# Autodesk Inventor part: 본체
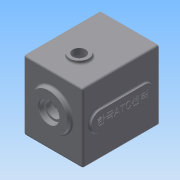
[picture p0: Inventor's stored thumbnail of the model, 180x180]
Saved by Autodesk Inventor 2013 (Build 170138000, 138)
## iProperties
Created: 2016-02
Part Number: 본체
Material: 알루미늄 6061
Document SubType Name: Modeling
Designer: mduedu
Density: 2.71 g/cm^3
Mass: 1515.93 g
Surface Area: 1077.08 cm^2
Volume: 559.383 cm^3
Author: mduedu
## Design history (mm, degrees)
sketch "스케치1"
  geometry: L1 (-47, -47)-(47, -47); L2 (47, -47)-(47, 63); L3 (47, 63)-(-47, 63); L4 (-47, 63)-(-47, -47); 2 further points
  constraints: 8 end point, 2 parallel, 1 horizontal, 1 midpoint, 1 perpendicular, 1 vertical alignment
  dimensions: "d0" = 94 distance of L2.end L3.end; "d155" = 110 distance of L1.end L2.end; "d156" = 47 distance from line of L1 point (0, 0)
extrude "돌출1" new body sketch "스케치1" distance "d2" = 120; taper "d3" = 0 deg
sketch "스케치3"
  geometry: L1 (47, -47)-(-47, -47) reference; L2 (47, 63)-(47, -47) reference; L3 (-47, 63)-(47, 63) reference; L4 (-47, -47)-(-47, 63) reference; L5 (37, 53)-(37, -37); L6 (37, -37)-(-37, -37); L7 (-37, -37)-(-37, 53); L8 (-37, 53)-(37, 53); 1 further point
  constraints: 8 end point, 3 other
  dimensions: "d226" = 10 distance between parallel lines of L8 L3
extrude "돌출3" cut sketch "스케치3" distance "d11" = 110; taper "d12" = 0 deg
sketch "스케치4"
  geometry: C1 r 21 at (0, 11); 1 further point
  constraints: 1 centre point, 1 vertical alignment
  dimensions: "d13" = 21 radius of C1; "d227" = 11 distance of point (0, 0) C1.centre
extrude "돌출4" join sketch "스케치4" distance "d16" = 7; taper "d17" = 0 deg
sketch "스케치5"
  geometry: C1 r 15 at (0, -20); 1 further point
  constraints: 1 centre point, 1 vertical alignment
  dimensions: "d18" = 15 radius of C1; "d20" = 20 distance of point (0, 0) C1.centre
extrude "돌출5" join sketch "스케치5" distance "d21" = 7; taper "d22" = 0 deg
sketch "스케치6"
  geometry: C1 r 30 at (0, 11); A1 r 21 centre (0, 11) between (8.978, -7.984) and (-8.978, -7.984) reference; 1 further point
  constraints: 1 centre point, 1 coincident
  dimensions: "d228" = 60 diameter of C1
extrude "돌출6" join sketch "스케치6" distance "d25" = 7; taper "d26" = -3 deg
hole "구멍1" diameter "d29" = 35; stored, may be unused: countersink angle "d33" = 90 deg, drill point angle "d35" = 0 deg; dims "d27" = 10, "d28" = 10, "d30" = 6, "d31" = 4, "d32" = 2, "d34" = 10
hole "구멍2" diameter "d38" = 22; stored, may be unused: countersink angle "d42" = 90 deg, drill point angle "d44" = 0 deg; dims "d36" = 10, "d37" = 10, "d39" = 6, "d40" = 4, "d41" = 2, "d43" = 7
hole "구멍3" diameter "d47" = 19; stored, may be unused: countersink angle "d51" = 90 deg, drill point angle "d53" = 0 deg; dims "d45" = 10, "d46" = 10, "d48" = 6, "d49" = 4, "d50" = 2, "d52" = 1
hole "구멍4" diameter "d56" = 32; stored, may be unused: countersink angle "d60" = 90 deg, drill point angle "d62" = 0 deg; dims "d57" = 6, "d58" = 4, "d59" = 2, "d61" = 8, "d220" = 10, "d221" = 10
hole "구멍5" diameter "d65" = 25; stored, may be unused: countersink angle "d69" = 90 deg, drill point angle "d71" = 0 deg; dims "d63" = 10, "d64" = 10, "d66" = 6, "d67" = 4, "d68" = 2, "d70" = 8
fillet "모깎기2" dims "d73" = 0.3
fillet "모깎기3" dims "d74" = 2
chamfer "모따기1" distance "d75" = 1; stored, may be unused: second distance "d76" = 2, angle "d77" = 45 deg
fillet "모깎기4" dims "d78" = 3
fillet "모깎기23" dims "d240" = 1
fillet "모깎기20" dims "d229" = 3
sketch "스케치23"
  geometry: L1 (-37, 53)-(37, 53) reference; L2 (37, 53)-(37, -37) reference; L3 (37, -37)-(-37, -37) reference; L4 (-37, -37)-(-37, 53) reference; L5 (44, -47)-(-44, -47) reference; L6 (47, 60)-(47, -44) reference; L7 (-44, 63)-(44, 63) reference; L8 (-47, -44)-(-47, 60) reference; C1 r 10 at (-37, 53); C2 r 10 at (37, 53); C3 r 10 at (-37, -37); C4 r 10 at (37, -37); A1 r 3 centre (-44, -44) between (-47, -44) and (-44, -47) reference; A2 r 3 centre (44, -44) between (44, -47) and (47, -44) reference; A3 r 3 centre (44, 60) between (47, 60) and (44, 63) reference; A4 r 3 centre (-44, 60) between (-44, 63) and (-47, 60) reference; 1 further point
  constraints: 4 centre point, 4 coincident, 3 equal radius
  dimensions: "d230" = 20 diameter of C1
extrude "돌출22" join sketch "스케치23" stored distance "d235" = 10; taper "d236" = 0 deg
fillet "모깎기21" dims "d237" = 3
node "작업 평면1"
fillet "모깎기22" dims "d239" = 1
sketch "스케치12"
  geometry: A1 r 10 centre (-37, 53) between (-34.692, 43.27) and (-27.27, 50.692) reference; A2 r 10 centre (37, 53) between (27.27, 50.692) and (34.692, 43.27) reference; A3 r 10 centre (37, -37) between (34.692, -27.27) and (27.27, -34.692) reference; A4 r 10 centre (-37, -37) between (-27.27, -34.692) and (-34.692, -27.27) reference; 5 further points
  constraints: 4 coincident
hole "구멍6" sketch "스케치12" at (-37, 53), (37, 53), (37, -37), (-37, -37) diameter "d122" = 3.242; stored, may be unused: countersink angle "d126" = 90 deg, drill point angle "d128" = 120 deg; dims "d123" = 7, "d124" = 4, "d125" = 2, "d127" = 9
sketch "스케치20"
  geometry: L1 (44, 0)-(-44, 0) reference; L2 (44, -120)-(-44, -120) reference; L3 (0, 0)-(0, -120); L4 (-44, -120)-(-44, 0) reference; L5 (44, 0)-(44, -120) reference; C1 r 10 at (0, -79)
  constraints: 2 end point, 1 centre point, 1 midpoint, 1 point on line
  dimensions: "d189" = 20 diameter of C1; "d190" = 41 distance from line of C1.centre L2
extrude "돌출19" cut sketch "스케치20" stored distance "d191" = 10; taper "d192" = 0 deg
sketch "스케치18"
  geometry: C1 r 15 at (0, -79); C2 r 10 at (0, -79) reference; 1 further point
  constraints: 1 centre point, 1 concentric
  dimensions: "d174" = 30 diameter of C1
extrude "돌출17" join sketch "스케치18" distance "d175" = 5; taper "d176" = 0 deg
fillet "모깎기16" dims "d177" = 3
sketch "스케치19"
  geometry: C1 r 15 at (24.351, 79); C2 r 10 at (24.351, 79) reference; 1 further point
  constraints: 1 centre point, 1 concentric
  dimensions: "d178" = 30 diameter of C1
extrude "돌출18" cut sketch "스케치19" distance "d181" = 5; taper "d182" = 0 deg
chamfer "모따기5" distance "d183" = 1; stored, may be unused: second distance "d184" = 2, angle "d185" = 45 deg
fillet "모깎기24" dims "d242" = 3, "d243" = 3
sketch "스케치24"
  geometry: L1 (-95, 67)-(-25, 67); L2 (-25, 67)-(-25, 37); L3 (-25, 37)-(-95, 37); L4 (-95, 37)-(-95, 67); L5 (0, 0)-(0, 104) reference; L6 (-95, 52)-(-25, 52); L7 (-60, 67)-(-60, 37); A1 r 15 centre (-95, 52) between (-95, 37) and (-95, 67); A2 r 15 centre (-25, 52) between (-25, 67) and (-25, 37); A3 r 15 centre (-25, 52) between (-25, 37) and (-25, 67); A4 r 15 centre (-95, 52) between (-95, 67) and (-95, 37); 2 further points
  constraints: 12 end point, 8 point on circle, 5 midpoint, 4 centre point, 2 parallel, 2 perpendicular, 1 horizontal, 1 horizontal alignment
  dimensions: "d244" = 60 distance between parallel lines of L7 L5; "d245" = 100 dimension on A2 A1; "d246" = 30 distance between parallel lines of L3 L1
extrude "돌출23" join sketch "스케치24" distance "d247" = 3; taper "d248" = 0 deg
fillet "모깎기25" dims "d249" = 3
sketch "스케치25"
  geometry: L1 (-25, 67)-(-95, 67) reference; L2 (-95, 37)-(-25, 37) reference; A1 r 15 centre (-95, 52) between (-95, 67) and (-95, 37) reference; A2 r 15 centre (-25, 52) between (-25, 37) and (-25, 67) reference; 3 further points
  constraints: 1 horizontal alignment, 1 midpoint, 1 vertical alignment, 1 other
feature "엠보싱3" sketch "스케치25" dims "d250" = 0.5, "d251" = 0
sketch "스케치26"
  geometry: L1 (14.367, 127)-(73.633, 127) reference; L2 (0, 0)-(88, 0) reference; L3 (88, 120)-(0, 120) reference; 5 further points
  constraints: 3 vertical alignment, 2 midpoint
  dimensions: "d252" = 35 distance from line of point (44, 35) L2; "d253" = 35 distance from line of point (44, 85) L3; "d254" = 50 distance of point (44, 35) point (44, 85) (derived)
hole "구멍8" sketch "스케치26" at (44, 85), (44, 35) diameter "d255" = 6.647; stored, may be unused: countersink angle "d259" = 90 deg, drill point angle "d261" = 118 deg; dims "d256" = 6, "d257" = 4, "d258" = 2, "d260" = 8
node "솔리드1"
node "투영된 루프1"
node "투영된 루프4"
node "투영된 루프5"
node "투영된 루프6"
